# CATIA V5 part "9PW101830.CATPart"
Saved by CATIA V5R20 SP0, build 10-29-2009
Part number: 9PW101830
Revision: ANY
Definition: UNKNOWN
Nomenclature: 9PW101830
Source: Unknown
Bounding box of the stored display mesh (mm): x -174.496 to 0, y -14.062 to 5, z -9.1 to 9.1
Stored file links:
  C:\Users\Utente\Desktop\IO LAVORO\3D X SITO CF\CUMSA\3D files PW\pw101830\pw101830_ejection\9PW101830.CATPart
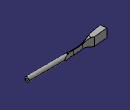
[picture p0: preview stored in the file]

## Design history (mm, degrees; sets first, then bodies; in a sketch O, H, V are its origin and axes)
Body1 "Chaflán4" (main body)
  Solid1: solid without history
